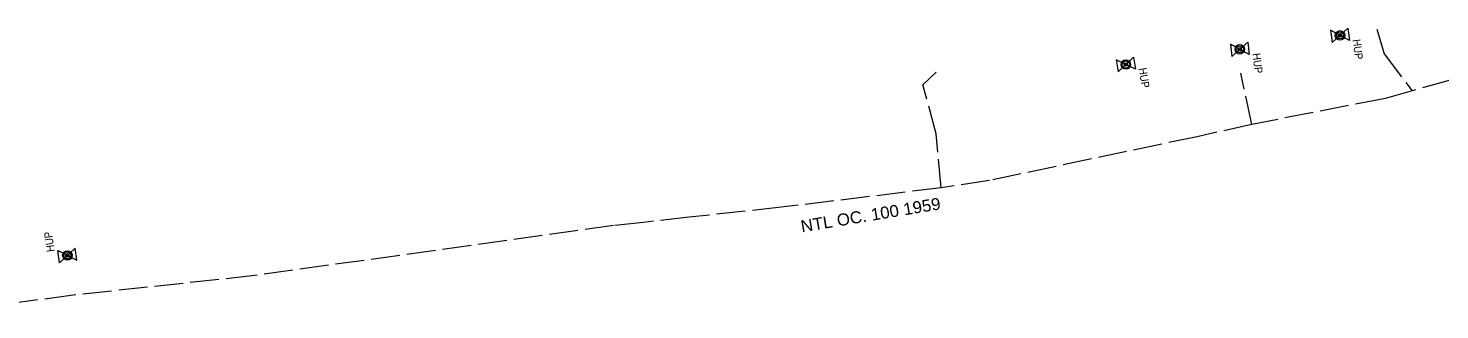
# Model space of a CAD drawing. Extents: x -688140 to -687678, y -1056859 to -1056384.
# Drawn here: x -687851.2 to -687762.9, y -1056565.5 to -1056547.9 of the extents above; entities that cross this region are included whole.
import ezdxf
from ezdxf.enums import TextEntityAlignment as Align

# ---------------------------------------------------------------- set-up
doc = ezdxf.new("R2010")
doc.units = 0
doc.header["$LTSCALE"] = 0.3
doc.linetypes.add('LONG_DASHED', pattern=[7.5, 6, -1.5])
for name, color, linetype, lineweight in [('12', 7, 'Continuous', 13), ('35', 7, 'LONG_DASHED', 13), ('50', 7, 'LONG_DASHED', 13)]:
    doc.layers.add(name, color=color, linetype=linetype, lineweight=lineweight)
doc.layers.add('15', color=7, linetype='Continuous')

msp = doc.modelspace()

# ---------------------------------------------------------------- linework, layer by layer
at = {"layer": '12'}
for p, q in [((-687769.772, -1056548.037), (-687769.678, -1056548.802)), ((-687768.596, -1056548.669), (-687769.772, -1056548.037)), ((-687768.69, -1056547.904), (-687769.678, -1056548.802)), ((-687768.69, -1056547.904), (-687768.596, -1056548.669)), ((-687776.035, -1056548.908), (-687775.941, -1056549.673)), ((-687774.859, -1056549.54), (-687776.035, -1056548.908)), ((-687774.953, -1056548.775), (-687775.941, -1056549.673)), ((-687774.953, -1056548.775), (-687774.859, -1056549.54)), ((-687782.091, -1056549.711), (-687783.047, -1056550.641)), ((-687782.091, -1056549.711), (-687781.971, -1056550.471)), ((-687783.167, -1056549.881), (-687783.047, -1056550.641)), ((-687781.971, -1056550.471), (-687783.167, -1056549.881)), ((-687849.313, -1056561.814), (-687848.127, -1056562.424)), ((-687849.206, -1056562.576), (-687849.313, -1056561.814)), ((-687849.206, -1056562.576), (-687848.234, -1056561.662)), ((-687848.127, -1056562.424), (-687848.234, -1056561.662))]:
    msp.add_line(p, q, dxfattribs=at)
for centre, radius in [((-687775.447, -1056549.224), 0.297), ((-687769.184, -1056548.353), 0.297), ((-687769.184, -1056548.353), 0.223), ((-687769.184, -1056548.353), 0.223), ((-687769.184, -1056548.353), 0.112), ((-687775.447, -1056549.224), 0.223), ((-687775.447, -1056549.224), 0.223), ((-687775.447, -1056549.224), 0.112), ((-687782.569, -1056550.176), 0.297), ((-687782.569, -1056550.176), 0.223), ((-687782.569, -1056550.176), 0.223), ((-687782.569, -1056550.176), 0.112), ((-687848.72, -1056562.119), 0.297), ((-687848.72, -1056562.119), 0.223), ((-687848.72, -1056562.119), 0.223), ((-687848.72, -1056562.119), 0.112)]:
    msp.add_circle(centre, radius, dxfattribs=at)
at = {"layer": '35'}
msp.add_lwpolyline([(-687755.8, -1056549.32), (-687764.681, -1056551.824), (-687766.44, -1056552.32), (-687774.69, -1056553.92), (-687778.12, -1056554.69), (-687791.08, -1056557.43), (-687794.12, -1056557.89), (-687804.12, -1056559.11), (-687809.86, -1056559.73), (-687812.72, -1056560.05), (-687814.58, -1056560.25), (-687837.01, -1056563.38), (-687848.35, -1056564.61), (-687855.26, -1056565.52)], dxfattribs=at)
at = {"layer": '50'}
msp.add_line((-687774.69, -1056553.92), (-687775.385, -1056550.719), dxfattribs=at)
for points in [[(-687766.886, -1056547.954), (-687766.42, -1056549.51), (-687764.681, -1056551.824)], [(-687794.12, -1056557.89), (-687794.42, -1056554.52), (-687795.25, -1056551.44), (-687794.419, -1056550.66)]]:
    msp.add_lwpolyline(points, dxfattribs=at)

# ---------------------------------------------------------------- texts
at = {"layer": '12', "width": 0.9}
for rotation, p in [(276.996, (-687768.318, -1056549.255)), (277.007, (-687774.58, -1056550.126)), (278.989, (-687781.672, -1056551.046)), (98.005, (-687849.602, -1056561.233))]:
    msp.add_text('HUP', height=0.5, rotation=rotation, dxfattribs=at).set_placement(p, align=Align.CENTER)
at = {"layer": '15', "width": 1.05}
msp.add_text('NTL OC. 100 1959', height=0.75, rotation=9.462, dxfattribs=at).set_placement((-687802.817, -1056560.681))

doc.saveas('drawing.dxf')
